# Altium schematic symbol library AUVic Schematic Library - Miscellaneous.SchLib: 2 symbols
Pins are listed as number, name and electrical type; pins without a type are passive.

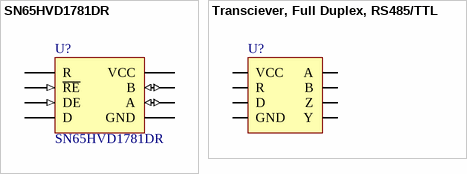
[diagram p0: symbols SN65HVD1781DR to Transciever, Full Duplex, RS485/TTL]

## SN65HVD1781DR
designator U?  Manufacturer Part Number: SN65HVD1781DR  (hidden comment: *)
IC TXRX RS485 FAULT-PROT 8-SOIC; Manufacturer: Texas Instruments; Number of Drivers/Receivers: 1/1; Duplex: Half; Receiver Hysteresis: 50mV; Data Rate: 1Mbps; Voltage - Supply: 3.15 V ~ 5.5 V
footprint SOIC127P490X175-8M (SOIC, 8-Leads, Body 4.90x3.90mm, Pitch 1.27mm, IPC Low Density)
pins: 1 R, 2 ~{RE} (in), 3 DE (in), 4 D, 5 GND (power), 6 A (io), 7 B (io), 8 VCC (power)

## Transciever, Full Duplex, RS485/TTL
designator U?  (value not drawn)
Transciever, Full Duplex, RS485/TTL
footprint SOIC127P780X200-8N (SOIC, 8-Leads, Body 6.20x5.30mm, Pitch 1.27mm, IPC Medium Density)
pins: 1 VCC, 2 R, 3 D, 4 GND, 5 Y, 6 Z, 7 B, 8 A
